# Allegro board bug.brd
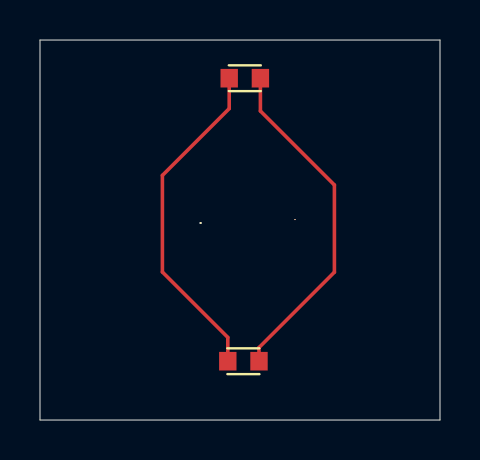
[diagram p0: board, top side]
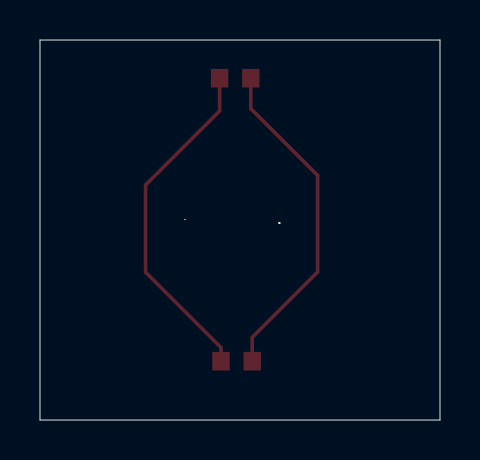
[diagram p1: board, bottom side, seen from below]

Outline 20 x 19 mm; copper layers: TOP, LAYER2, LAYER3, BOTTOM. Coordinates in mm from the lower left corner of the outline.
Outline path: 0,19 0,0 20,0 20,19 0,19

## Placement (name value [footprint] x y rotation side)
NOREF  -  [unnamed]  8.03 9.85 0 top
NOREF#2  -  [unnamed]  12.75 10.02 0 top
R1  1K  [RESC1608X55N]  9.46 17.09 0 top
R2  1K  [RESC1608X55N]  9.39 2.94 0 top

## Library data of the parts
R1 R2 = RESISTOR_5: tolerance: 5%

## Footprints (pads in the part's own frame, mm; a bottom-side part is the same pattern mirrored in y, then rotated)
RESC1608X55N
  rect 0.87x0.93 smd: 1(0,0) 2(1.56,0)
unnamed
  round 0.1 hole 1.57 unplated: (0,0)

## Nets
ONE: R1.1 R2.1
TWO: R1.2 R2.2

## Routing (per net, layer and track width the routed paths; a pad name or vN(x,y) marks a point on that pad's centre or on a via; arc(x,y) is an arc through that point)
ONE: length 16.9
  TOP w0.18: R1.1 9.46,15.57 6.12,12.23 6.12,7.4 9.39,4.13 R2.1
TWO: length 17.2
  TOP w0.18: R1.2 11.02,15.45 14.72,11.75 14.72,7.39 10.95,3.62 R2.2
